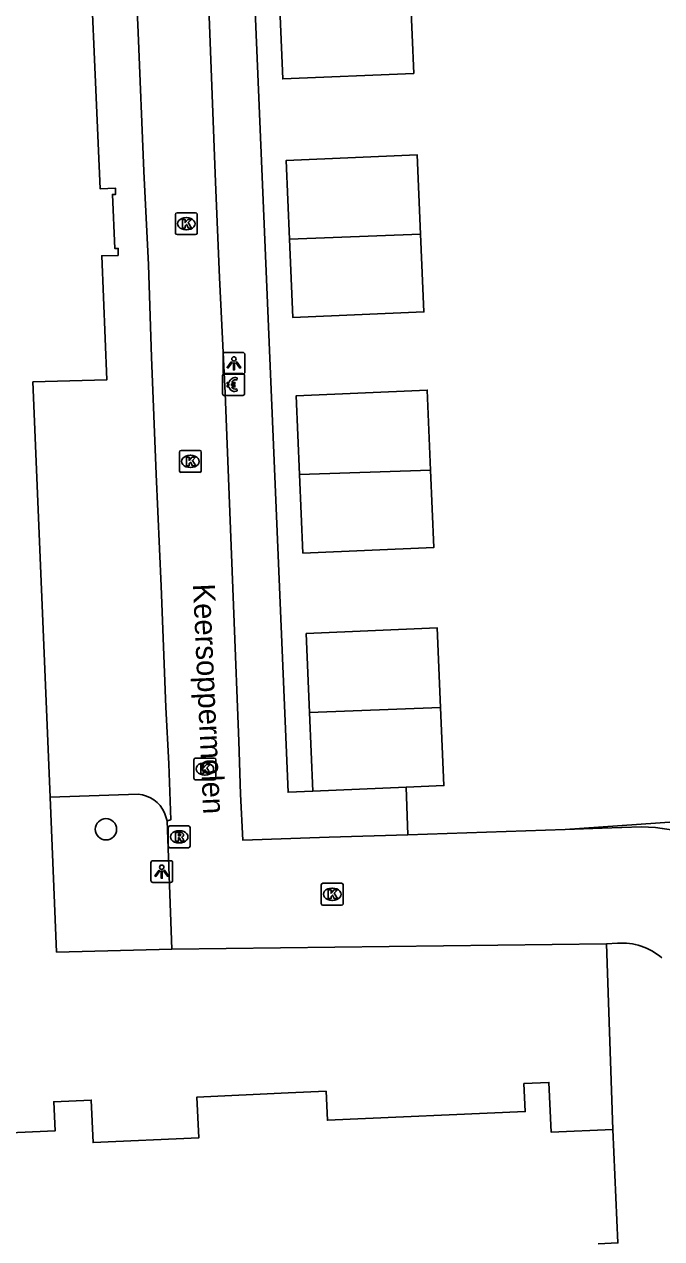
# Model space of a CAD drawing. Extents: x 161243 to 161752, y 384138 to 384885.
# Drawn here: x 161327.9 to 161357.1, y 384187.6 to 384243.2 of the extents above; entities that cross this region are included whole.
import ezdxf

# ---------------------------------------------------------------- set-up
doc = ezdxf.new("R2010")
doc.units = 0
for name, color, linetype in [('IMGEO_Betaalautomaat', 7, 'Continuous'), ('IMGEO_Boom', 7, 'Continuous'), ('IMGEO_Groenvoorziening', 7, 'Continuous'), ('IMGEO_Kolk', 7, 'Continuous'), ('IMGEO_Lichtpunt', 7, 'Continuous'), ('IMGEO_Openbare_ruimte_label', 7, 'Continuous'), ('IMGEO_Pand', 7, 'Continuous'), ('IMGEO_Parkeervlak_open', 7, 'Continuous'), ('IMGEO_Rijbaan_lokaal_open', 7, 'Continuous'), ('IMGEO_Rioolput', 7, 'Continuous'), ('IMGEO_Voetpad_open', 7, 'Continuous')]:
    doc.layers.add(name, color=color, linetype=linetype)

msp = doc.modelspace()

# ---------------------------------------------------------------- linework, layer by layer
at = {"layer": 'IMGEO_Betaalautomaat'}
for p, q in [((161337.014, 384226.321), (161337.014, 384227.162)), ((161337.014, 384227.162), (161337.014, 384226.321)), ((161337.089, 384227.245), (161337.93, 384227.245)), ((161337.93, 384227.245), (161337.089, 384227.245)), ((161337.297, 384226.709), (161337.297, 384226.777)), ((161337.418, 384226.777), (161337.418, 384226.709)), ((161337.676, 384227.05), (161337.659, 384226.95)), ((161338.013, 384227.171), (161338.013, 384226.33)), ((161338.013, 384226.33), (161338.013, 384227.171)), ((161337.939, 384226.246), (161337.098, 384226.246)), ((161337.098, 384226.246), (161337.939, 384226.246)), ((161337.663, 384226.544), (161337.685, 384226.457))]:
    msp.add_line(p, q, dxfattribs=at)
for points in [[(161337.297, 384226.777), (161337.228, 384226.777), (161337.228, 384226.846), (161337.307, 384226.846)], [(161337.429, 384226.846), (161337.576, 384226.846), (161337.576, 384226.777), (161337.418, 384226.777)], [(161337.302, 384226.64), (161337.228, 384226.64), (161337.228, 384226.709), (161337.297, 384226.709)], [(161337.418, 384226.709), (161337.576, 384226.709), (161337.576, 384226.64), (161337.432, 384226.64)]]:
    msp.add_lwpolyline(points, dxfattribs=at)
for centre, radius, start, end in [((161337.092, 384227.168), 0.0779, 92.4484, 184.2845), ((161337.092, 384227.168), 0.0779, 92.4484, 184.2845), ((161337.59, 384226.77), 0.293, 73.014, 165.0139), ((161337.596, 384226.783), 0.179, 69.3236, 159.5683), ((161337.936, 384227.168), 0.0779, 2.4484, 94.2845), ((161337.936, 384227.168), 0.0779, 2.4484, 94.2845), ((161337.092, 384226.324), 0.0779, 182.4484, 274.2845), ((161337.092, 384226.324), 0.0779, 182.4484, 274.2845), ((161337.563, 384226.695), 0.267, 191.8096, 297.0389), ((161337.596, 384226.71), 0.179, 202.7625, 291.8693), ((161337.936, 384226.324), 0.0779, 272.4484, 4.2845), ((161337.936, 384226.324), 0.0779, 272.4484, 4.2845)]:
    msp.add_arc(centre, radius, start, end, dxfattribs=at)
at = {"layer": 'IMGEO_Boom'}
msp.add_circle((161331.674, 384206.391), 0.489, dxfattribs=at)
at = {"layer": 'IMGEO_Groenvoorziening'}
for points in [[(161334.694, 384200.909), (161329.416, 384200.768), (161329.121, 384207.854)], [(161352.693, 384206.382), (161359.441, 384206.859)], [(161354.879, 384192.653), (161354.591, 384201.143)]]:
    msp.add_lwpolyline(points, dxfattribs=at)
at = {"layer": 'IMGEO_Kolk'}
for p, q in [((161334.851, 384233.682), (161334.851, 384234.534)), ((161334.926, 384234.608), (161335.778, 384234.608)), ((161335.852, 384234.534), (161335.852, 384233.682)), ((161335.339, 384234.388), (161335.364, 384234.388)), ((161335.778, 384233.608), (161334.926, 384233.608)), ((161335.362, 384233.828), (161335.337, 384233.828)), ((161335.037, 384222.802), (161335.037, 384223.654)), ((161335.112, 384223.728), (161335.964, 384223.728)), ((161335.525, 384223.508), (161335.55, 384223.508)), ((161336.038, 384223.654), (161336.038, 384222.802)), ((161335.548, 384222.948), (161335.523, 384222.948)), ((161335.964, 384222.728), (161335.112, 384222.728)), ((161335.701, 384208.724), (161335.701, 384209.576)), ((161335.776, 384209.65), (161336.628, 384209.65)), ((161336.702, 384209.576), (161336.702, 384208.724)), ((161336.189, 384209.43), (161336.214, 384209.43)), ((161336.628, 384208.65), (161335.776, 384208.65)), ((161336.212, 384208.87), (161336.187, 384208.87)), ((161341.53, 384202.99), (161341.53, 384203.842)), ((161341.605, 384203.916), (161342.457, 384203.916)), ((161342.018, 384203.696), (161342.043, 384203.696)), ((161342.531, 384203.842), (161342.531, 384202.99)), ((161342.457, 384202.916), (161341.605, 384202.916)), ((161342.041, 384203.136), (161342.016, 384203.136))]:
    msp.add_line(p, q, dxfattribs=at)
for points in [[(161334.851, 384233.682), (161334.851, 384234.534)], [(161334.926, 384234.608), (161335.778, 384234.608)], [(161335.852, 384234.534), (161335.852, 384233.682)], [(161335.172, 384234.308), (161335.295, 384234.308), (161335.295, 384234.157), (161335.425, 384234.308), (161335.589, 384234.308), (161335.443, 384234.157), (161335.596, 384233.908), (161335.444, 384233.908), (161335.359, 384234.072), (161335.295, 384234.005), (161335.295, 384233.908), (161335.172, 384233.908), (161335.172, 384234.308)], [(161335.778, 384233.608), (161334.926, 384233.608)], [(161335.037, 384222.802), (161335.037, 384223.654)], [(161335.112, 384223.728), (161335.964, 384223.728)], [(161335.358, 384223.428), (161335.481, 384223.428), (161335.481, 384223.277), (161335.611, 384223.428), (161335.775, 384223.428), (161335.629, 384223.277), (161335.782, 384223.028), (161335.63, 384223.028), (161335.545, 384223.192), (161335.481, 384223.125), (161335.481, 384223.028), (161335.358, 384223.028), (161335.358, 384223.428)], [(161336.038, 384223.654), (161336.038, 384222.802)], [(161335.964, 384222.728), (161335.112, 384222.728)], [(161335.701, 384208.724), (161335.701, 384209.576)], [(161335.776, 384209.65), (161336.628, 384209.65)], [(161336.702, 384209.576), (161336.702, 384208.724)], [(161336.022, 384209.35), (161336.145, 384209.35), (161336.145, 384209.199), (161336.275, 384209.35), (161336.439, 384209.35), (161336.293, 384209.199), (161336.446, 384208.95), (161336.294, 384208.95), (161336.209, 384209.114), (161336.145, 384209.047), (161336.145, 384208.95), (161336.022, 384208.95), (161336.022, 384209.35)], [(161336.628, 384208.65), (161335.776, 384208.65)], [(161341.53, 384202.99), (161341.53, 384203.842)], [(161341.605, 384203.916), (161342.457, 384203.916)], [(161341.851, 384203.616), (161341.974, 384203.616), (161341.974, 384203.465), (161342.104, 384203.616), (161342.268, 384203.616), (161342.122, 384203.465), (161342.275, 384203.216), (161342.123, 384203.216), (161342.038, 384203.38), (161341.974, 384203.313), (161341.974, 384203.216), (161341.851, 384203.216), (161341.851, 384203.616)], [(161342.531, 384203.842), (161342.531, 384202.99)], [(161342.457, 384202.916), (161341.605, 384202.916)]]:
    msp.add_lwpolyline(points, dxfattribs=at)
for centre, start, end in [((161334.928, 384234.532), 91.552, 178.448), ((161334.928, 384234.532), 91.552, 178.448), ((161335.776, 384234.532), 1.552, 88.448), ((161335.776, 384234.532), 1.552, 88.448), ((161334.928, 384233.684), 181.552, 268.448), ((161334.928, 384233.684), 181.552, 268.448), ((161335.776, 384233.684), 271.552, 358.448), ((161335.776, 384233.684), 271.552, 358.448), ((161335.114, 384223.652), 91.552, 178.448), ((161335.114, 384223.652), 91.552, 178.448), ((161335.962, 384223.652), 1.552, 88.448), ((161335.962, 384223.652), 1.552, 88.448), ((161335.114, 384222.804), 181.552, 268.448), ((161335.114, 384222.804), 181.552, 268.448), ((161335.962, 384222.804), 271.552, 358.448), ((161335.962, 384222.804), 271.552, 358.448), ((161335.778, 384209.574), 91.552, 178.448), ((161335.778, 384209.574), 91.552, 178.448), ((161336.626, 384209.574), 1.552, 88.448), ((161336.626, 384209.574), 1.552, 88.448), ((161335.778, 384208.726), 181.552, 268.448), ((161335.778, 384208.726), 181.552, 268.448), ((161336.626, 384208.726), 271.552, 358.448), ((161336.626, 384208.726), 271.552, 358.448), ((161341.607, 384203.84), 91.552, 178.448), ((161341.607, 384203.84), 91.552, 178.448), ((161342.455, 384203.84), 1.552, 88.448), ((161342.455, 384203.84), 1.552, 88.448), ((161341.607, 384202.992), 181.552, 268.448), ((161341.607, 384202.992), 181.552, 268.448), ((161342.455, 384202.992), 271.552, 358.448), ((161342.455, 384202.992), 271.552, 358.448)]:
    msp.add_arc(centre, 0.0765, start, end, dxfattribs=at)
for centre, major_axis, ratio, start_param, end_param in [((161335.338, 384234.108), (-0.387, 0.002), 0.722429, 4.712389, 7.853982), ((161335.363, 384234.108), (-0.39, 0.002), 0.717154, 1.570796, 4.712389), ((161335.524, 384223.228), (-0.387, 0.002), 0.722429, 4.712389, 7.853982), ((161335.549, 384223.228), (-0.39, 0.002), 0.717154, 1.570796, 4.712389), ((161336.188, 384209.15), (-0.387, 0.002), 0.722429, 4.712389, 7.853982), ((161336.213, 384209.15), (-0.39, 0.002), 0.717154, 1.570796, 4.712389), ((161342.017, 384203.416), (-0.387, 0.002), 0.722429, 4.712389, 7.853982), ((161342.042, 384203.416), (-0.39, 0.002), 0.717154, 1.570796, 4.712389)]:
    msp.add_ellipse(centre, major_axis=major_axis, ratio=ratio, start_param=start_param, end_param=end_param, dxfattribs=at)
at = {"layer": 'IMGEO_Lichtpunt'}
for p, q in [((161337.033, 384228.122), (161337.033, 384227.315)), ((161337.033, 384228.122), (161337.033, 384227.315)), ((161337.935, 384228.217), (161337.127, 384228.217)), ((161337.935, 384228.217), (161337.127, 384228.217)), ((161338.029, 384227.315), (161338.029, 384228.122)), ((161338.029, 384227.315), (161338.029, 384228.122)), ((161337.127, 384227.221), (161337.935, 384227.221)), ((161337.127, 384227.221), (161337.935, 384227.221)), ((161333.728, 384204.857), (161333.728, 384204.05)), ((161333.728, 384204.857), (161333.728, 384204.05)), ((161334.63, 384204.952), (161333.822, 384204.952)), ((161334.63, 384204.952), (161333.822, 384204.952)), ((161334.724, 384204.05), (161334.724, 384204.857)), ((161334.724, 384204.05), (161334.724, 384204.857)), ((161333.822, 384203.956), (161334.63, 384203.956)), ((161333.822, 384203.956), (161334.63, 384203.956))]:
    msp.add_line(p, q, dxfattribs=at)
for points in [[(161337.407, 384227.786), (161337.446, 384227.758), (161337.258, 384227.496), (161337.22, 384227.523), (161337.407, 384227.786)], [(161337.509, 384227.738), (161337.556, 384227.738), (161337.556, 384227.416), (161337.509, 384227.416), (161337.509, 384227.738)], [(161337.619, 384227.758), (161337.657, 384227.785), (161337.844, 384227.523), (161337.805, 384227.495), (161337.619, 384227.758)], [(161334.102, 384204.521), (161334.141, 384204.493), (161333.953, 384204.231), (161333.915, 384204.258), (161334.102, 384204.521)], [(161334.314, 384204.493), (161334.352, 384204.52), (161334.539, 384204.258), (161334.5, 384204.23), (161334.314, 384204.493)], [(161334.204, 384204.473), (161334.251, 384204.473), (161334.251, 384204.151), (161334.204, 384204.151), (161334.204, 384204.473)]]:
    msp.add_lwpolyline(points, dxfattribs=at)
for centre in [(161337.532, 384227.92), (161334.227, 384204.655)]:
    msp.add_circle(centre, 0.0994, dxfattribs=at)
for centre, start, end in [((161337.127, 384228.122), 90, 180), ((161337.127, 384228.122), 90, 180), ((161337.935, 384228.122), 0, 90), ((161337.935, 384228.122), 0, 90), ((161337.127, 384227.315), 180, 270), ((161337.127, 384227.315), 180, 270), ((161337.935, 384227.315), 270, 0), ((161337.935, 384227.315), 270, 360), ((161333.822, 384204.857), 90, 180), ((161333.822, 384204.857), 90, 180), ((161334.63, 384204.857), 0, 90), ((161334.63, 384204.857), 0, 90), ((161333.822, 384204.05), 180, 270), ((161333.822, 384204.05), 180, 270), ((161334.63, 384204.05), 270, 0), ((161334.63, 384204.05), 270, 360)]:
    msp.add_arc(centre, 0.0946, start, end, dxfattribs=at)
at = {"layer": 'IMGEO_Pand'}
for points in [[(161345.608, 384244.531), (161345.759, 384240.988), (161339.764, 384240.732), (161339.611, 384244.328)], [(161340.076, 384233.398), (161339.922, 384237.005), (161345.917, 384237.261), (161346.072, 384233.628)], [(161346.072, 384233.628), (161346.224, 384230.068), (161340.229, 384229.812), (161340.076, 384233.398)], [(161340.076, 384233.398), (161346.072, 384233.628)], [(161340.535, 384222.628), (161340.381, 384226.235), (161346.376, 384226.491), (161346.532, 384222.833)], [(161346.532, 384222.833), (161346.683, 384219.288), (161340.688, 384219.032), (161340.535, 384222.628)], [(161340.535, 384222.628), (161346.532, 384222.833)], [(161340.994, 384211.741), (161340.84, 384215.348), (161346.835, 384215.604), (161346.991, 384211.96)], [(161340.994, 384211.741), (161346.991, 384211.96)], [(161341.148, 384208.134), (161340.994, 384211.741)], [(161346.991, 384211.96), (161347.143, 384208.39), (161345.413, 384208.316)], [(161341.148, 384208.134), (161345.413, 384208.316)], [(161320.36, 384192.186), (161329.341, 384192.58), (161329.282, 384193.919), (161330.996, 384193.995), (161331.081, 384192.05), (161335.919, 384192.262), (161335.837, 384194.134), (161340.012, 384194.319), (161341.751, 384194.396), (161341.809, 384193.069), (161350.862, 384193.467), (161350.806, 384194.75), (161351.948, 384194.8), (161352.047, 384192.529), (161354.879, 384192.653)], [(161354.879, 384192.653), (161355.107, 384187.458), (161354.21, 384187.419)]]:
    msp.add_lwpolyline(points, dxfattribs=at)
at = {"layer": 'IMGEO_Parkeervlak_open'}
for points in [[(161329.121, 384207.854), (161328.33, 384226.87), (161331.708, 384226.956), (161331.483, 384232.641), (161332.229, 384232.66), (161332.238, 384232.98), (161332.074, 384232.979), (161331.97, 384235.447), (161332.105, 384235.442), (161332.113, 384235.728), (161331.409, 384235.703), (161330.784, 384250), (161329.521, 384278.565)], [(161329.121, 384207.854), (161333.153, 384207.992)], [(161334.36, 384207.144), (161334.479, 384206.784)]]:
    msp.add_lwpolyline(points, dxfattribs=at)
msp.add_arc((161333.032, 384206.537), 1.46, 24.5635, 85.2551, dxfattribs=at)
at = {"layer": 'IMGEO_Rijbaan_lokaal_open'}
for points in [[(161345.496, 384206.142), (161341.894, 384206.028), (161337.932, 384205.899), (161337.833, 384208.001), (161337.76, 384210.422), (161337.527, 384216.256), (161337.129, 384226.353), (161336.868, 384231.648), (161336.684, 384236.002), (161336.225, 384248.01), (161336.134, 384250), (161335.741, 384258.44), (161335.543, 384263.223), (161335.328, 384268.908), (161335.107, 384273.512), (161334.887, 384278.846), (161333.256, 384278.821), (161331.584, 384278.687)], [(161331.584, 384278.687), (161331.739, 384274.994), (161331.985, 384270.03), (161332.284, 384263.343), (161332.501, 384257.819), (161332.832, 384250), (161332.915, 384248.051), (161333.147, 384242.867), (161333.411, 384236.512), (161333.617, 384232.219), (161333.763, 384228.005), (161333.973, 384222.651), (161334.206, 384217.517), (161334.413, 384211.983), (161334.554, 384209.391), (161334.636, 384206.829), (161334.479, 384206.784)], [(161334.479, 384206.784), (161334.694, 384200.909)], [(161352.693, 384206.382), (161345.496, 384206.142)], [(161356.182, 384206.499), (161354.382, 384206.439), (161352.693, 384206.382)], [(161334.694, 384200.909), (161354.591, 384201.143)], [(161354.591, 384201.143), (161355.082, 384201.175)]]:
    msp.add_lwpolyline(points, dxfattribs=at)
for centre, radius, start, end in [((161356.158, 384199.791), 6.709, 46.2683, 89.7909), ((161355.299, 384198.424), 2.759, 48.9134, 94.5048), ((161353.715, 384187.917), 4.717, 278.2883, 359.454)]:
    msp.add_arc(centre, radius, start, end, dxfattribs=at)
at = {"layer": 'IMGEO_Rioolput'}
for p, q in [((161334.525, 384205.619), (161334.525, 384206.471)), ((161334.6, 384206.545), (161335.452, 384206.545)), ((161335.013, 384206.325), (161335.038, 384206.325)), ((161335.526, 384206.471), (161335.526, 384205.619)), ((161335.036, 384205.765), (161335.011, 384205.765)), ((161335.452, 384205.545), (161334.6, 384205.545))]:
    msp.add_line(p, q, dxfattribs=at)
for points in [[(161334.525, 384205.619), (161334.525, 384206.471)], [(161334.6, 384206.545), (161335.452, 384206.545)], [(161335.114, 384206.243), (161334.862, 384206.245), (161334.862, 384205.845)], [(161335.04, 384206.164), (161334.986, 384206.164), (161334.986, 384206.083)], [(161335.526, 384206.471), (161335.526, 384205.619)], [(161334.862, 384205.845), (161334.986, 384205.845), (161334.986, 384206.007), (161334.997, 384206.007)], [(161334.986, 384206.083), (161335.038, 384206.083)], [(161335.044, 384205.978), (161335.115, 384205.845), (161335.255, 384205.845), (161335.19, 384205.971)], [(161335.452, 384205.545), (161334.6, 384205.545)]]:
    msp.add_lwpolyline(points, dxfattribs=at)
for centre, radius, start, end in [((161334.602, 384206.469), 0.0765, 91.552, 178.448), ((161334.602, 384206.469), 0.0765, 91.552, 178.448), ((161335.046, 384206.068), 0.0964, 77.0061, 93.1865), ((161335.06, 384206.125), 0.0378, 276.6634, 79.6772), ((161335.113, 384206.133), 0.109, 350.3612, 89.416), ((161335.45, 384206.469), 0.0765, 1.552, 88.448), ((161335.45, 384206.469), 0.0765, 1.552, 88.448), ((161334.602, 384205.621), 0.0765, 181.552, 268.448), ((161334.602, 384205.621), 0.0765, 181.552, 268.448), ((161334.996, 384205.954), 0.0533, 26.0293, 88.6989), ((161335.022, 384206.272), 0.19, 274.7715, 282.9687), ((161335.111, 384206.133), 0.112, 277.5842, 350.9817), ((161335.095, 384205.918), 0.108, 29.5134, 73.7905), ((161335.45, 384205.621), 0.0765, 271.552, 358.448), ((161335.45, 384205.621), 0.0765, 271.552, 358.448)]:
    msp.add_arc(centre, radius, start, end, dxfattribs=at)
for centre, major_axis, ratio, start_param, end_param in [((161335.012, 384206.045), (-0.387, 0.002), 0.722429, 4.712389, 7.853982), ((161335.037, 384206.045), (-0.39, 0.002), 0.717154, 1.570796, 4.712389)]:
    msp.add_ellipse(centre, major_axis=major_axis, ratio=ratio, start_param=start_param, end_param=end_param, dxfattribs=at)
at = {"layer": 'IMGEO_Voetpad_open'}
for points in [[(161336.819, 384283.698), (161338.239, 384250), (161340.006, 384208.085), (161341.148, 384208.134)], [(161345.413, 384208.316), (161345.496, 384206.142)]]:
    msp.add_lwpolyline(points, dxfattribs=at)

# ---------------------------------------------------------------- texts
at = {"layer": 'IMGEO_Openbare_ruimte_label'}
msp.add_text('Keersoppermolen', height=1, rotation=272.5791, dxfattribs=at).set_placement((161335.655, 384217.611))

doc.saveas('drawing.dxf')
